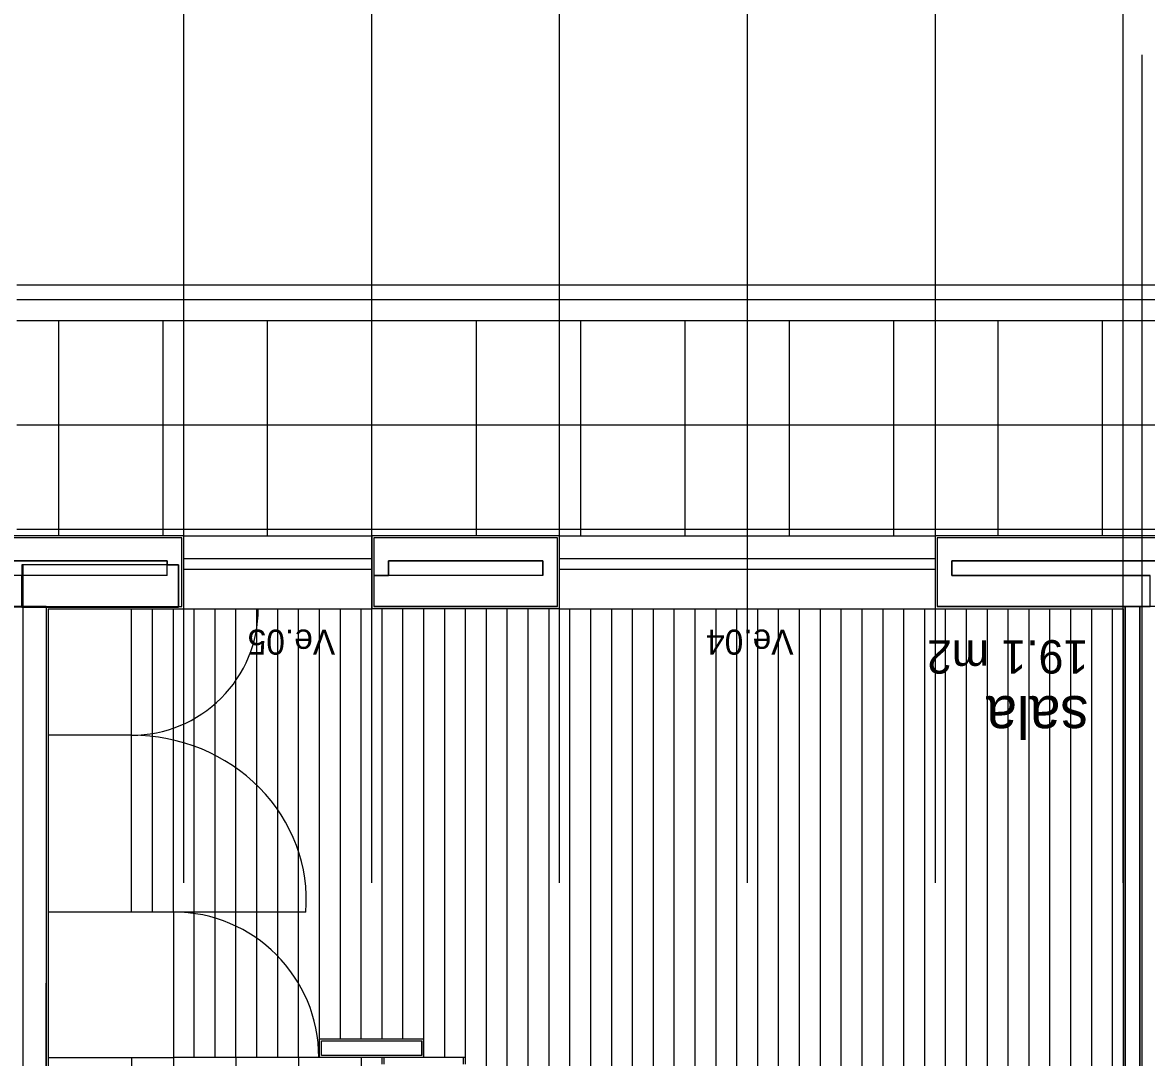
# Model space of a CAD drawing. Extents: x 1248 to 1356, y -443 to -224.
# Drawn here: x 1334.72 to 1340.11, y -234.42 to -229.47 of the extents above; entities that cross this region are included whole.
import ezdxf

# ---------------------------------------------------------------- set-up
doc = ezdxf.new("R2010")
doc.units = 0
for name, color, linetype in [('corte', 7, 'Continuous'), ('estereoctomias', 7, 'Continuous'), ('Level 1', 7, 'Continuous'), ('Level 10', 7, 'Continuous'), ('Level 13', 7, 'Continuous'), ('Level 2', 7, 'Continuous'), ('Level 3', 7, 'Continuous'), ('Level 4', 7, 'Continuous'), ('Level 40', 7, 'Continuous'), ('Level 60', 7, 'Continuous'), ('revestimentos', 7, 'Continuous'), ('vermelhos-cont', 7, 'Continuous'), ('vermelhos-tracej', 7, 'Continuous')]:
    doc.layers.add(name, color=color, linetype=linetype)

msp = doc.modelspace()

# ---------------------------------------------------------------- linework, layer by layer
at = {"layer": 'corte'}
for p, q in [((1335.484, -231.934), (1333.704, -231.934)), ((1337.284, -231.934), (1336.404, -231.934)), ((1340.884, -231.934), (1339.1033, -231.934)), ((1335.4133, -232.044), (1333.774, -232.044)), ((1337.214, -232.044), (1336.474, -232.044)), ((1340.814, -232.044), (1339.1733, -232.044)), ((1334.7233, -238.544), (1334.7233, -232.0639)), ((1335.4133, -232.114), (1334.7233, -232.114)), ((1337.214, -232.114), (1336.474, -232.114)), ((1339.1733, -232.114), (1340.1183, -232.114)), ((1334.8333, -232.264), (1333.704, -232.264)), ((1337.284, -232.264), (1336.404, -232.264)), ((1340.234, -232.264), (1339.1033, -232.264)), ((1340.0033, -238.424), (1340.0033, -232.264)), ((1340.0733, -236.7713), (1340.0733, -232.264))]:
    msp.add_line(p, q, dxfattribs=at)
msp.add_lwpolyline([(1335.4675, -232.0639), (1334.7175, -232.0639), (1334.7175, -232.2657), (1335.4675, -232.2657)], close=True, dxfattribs=at)
at = {"layer": 'estereoctomias'}
for points in [[(1334.7175, -232.2657), (1334.7175, -232.114), (1333.774, -232.114), (1333.774, -232.044), (1335.4133, -232.044), (1335.4133, -232.0639), (1335.4675, -232.0639), (1335.4675, -232.264), (1335.484, -232.264), (1335.484, -231.934), (1333.704, -231.934), (1333.704, -232.264)], [(1337.284, -232.264), (1337.284, -231.934), (1336.404, -231.934), (1336.404, -232.114), (1336.474, -232.114), (1336.474, -232.044), (1337.214, -232.044), (1337.214, -232.114), (1336.404, -232.114), (1336.404, -232.264)], [(1340.884, -232.264), (1340.884, -231.934), (1339.1033, -231.934), (1339.1033, -232.264), (1340.124, -232.264), (1340.124, -232.114), (1339.1733, -232.114), (1339.1733, -232.044), (1340.814, -232.044), (1340.814, -232.079), (1340.8683, -232.079), (1340.8683, -232.2657)], [(1334.8333, -235.8713), (1334.7233, -235.8713), (1334.7233, -232.264), (1334.8333, -232.264), (1334.8325, -235.8713)], [(1340.0733, -232.264), (1340.0733, -235.8713), (1340.0033, -235.8713), (1340.0033, -232.264)], [(1336.6333, -234.344), (1336.6333, -234.414), (1336.1533, -234.414), (1336.1533, -234.344)]]:
    msp.add_lwpolyline(points, close=True, dxfattribs=at)
at = {"layer": 'Level 1'}
for p, q in [((1335.484, -232.264), (1335.484, -231.934)), ((1336.404, -231.934), (1336.404, -232.264)), ((1337.284, -232.264), (1337.284, -231.934)), ((1339.1033, -231.934), (1339.1033, -232.264)), ((1335.4133, -232.114), (1335.4133, -232.044)), ((1336.474, -232.044), (1336.474, -232.114)), ((1337.214, -232.114), (1337.214, -232.044)), ((1339.1733, -232.044), (1339.1733, -232.114)), ((1334.7233, -232.114), (1334.7233, -232.114)), ((1334.8333, -232.264), (1335.484, -232.264)), ((1334.8333, -232.264), (1334.8333, -238.544)), ((1340.0033, -232.264), (1340.0033, -238.424)), ((1336.1533, -234.414), (1336.1533, -234.344)), ((1336.1533, -234.344), (1336.6333, -234.344)), ((1336.6333, -234.414), (1336.6333, -234.344)), ((1336.8433, -234.424), (1336.1433, -234.424)), ((1336.6333, -234.414), (1336.1533, -234.414)), ((1336.4433, -234.456), (1336.4433, -234.424)), ((1336.4533, -234.456), (1336.4533, -234.424)), ((1336.8333, -234.456), (1336.8333, -234.424)), ((1336.8433, -234.456), (1336.8433, -234.424))]:
    msp.add_line(p, q, dxfattribs=at)
at = {"layer": 'Level 10'}
for p, q in [((1340.0933, -230.894), (1334.6933, -230.894)), ((1334.8933, -230.894), (1334.8933, -231.924)), ((1335.3933, -230.894), (1335.3933, -231.924)), ((1335.8933, -230.894), (1335.8933, -231.924)), ((1336.3933, -230.894), (1336.3933, -231.924)), ((1336.8933, -230.894), (1336.8933, -231.924)), ((1337.3933, -230.894), (1337.3933, -231.924)), ((1337.8933, -230.894), (1337.8933, -231.924)), ((1338.3933, -230.894), (1338.3933, -231.924)), ((1338.8933, -230.894), (1338.8933, -231.924)), ((1339.3933, -230.894), (1339.3933, -231.924)), ((1339.8933, -230.894), (1339.8933, -231.924)), ((1345.4933, -230.894), (1340.0933, -230.894)), ((1340.0933, -231.394), (1334.6933, -231.394)), ((1345.4933, -231.394), (1340.0933, -231.394)), ((1340.0933, -231.894), (1334.6933, -231.894)), ((1345.4933, -231.894), (1340.0933, -231.894)), ((1335.3433, -233.727), (1335.3433, -232.274)), ((1335.4433, -233.727), (1335.4433, -232.274)), ((1335.5433, -234.424), (1335.5433, -232.274)), ((1335.6433, -234.424), (1335.6433, -232.274)), ((1335.7433, -234.424), (1335.7433, -232.274)), ((1335.8433, -234.424), (1335.8433, -232.274)), ((1335.9433, -234.424), (1335.9433, -232.274)), ((1336.0433, -234.424), (1336.0433, -232.274)), ((1336.1433, -234.334), (1336.1433, -232.274)), ((1336.2433, -234.334), (1336.2433, -232.274)), ((1336.3433, -234.334), (1336.3433, -232.274)), ((1336.4433, -234.334), (1336.4433, -232.274)), ((1336.5433, -234.334), (1336.5433, -232.274)), ((1336.6433, -234.334), (1336.6433, -232.274)), ((1336.7433, -234.424), (1336.7433, -232.274)), ((1336.8433, -234.424), (1336.8433, -232.274)), ((1336.9433, -238.409), (1336.9433, -232.274)), ((1337.0433, -238.409), (1337.0433, -232.274)), ((1337.1433, -238.409), (1337.1433, -232.274)), ((1337.2433, -238.409), (1337.2433, -232.274)), ((1337.3433, -238.409), (1337.3433, -232.274)), ((1337.4433, -238.409), (1337.4433, -232.274)), ((1337.5433, -236.624), (1337.5433, -232.274)), ((1337.6433, -236.624), (1337.6433, -232.274)), ((1337.7433, -236.624), (1337.7433, -232.274)), ((1337.8433, -236.624), (1337.8433, -232.274)), ((1337.9433, -236.624), (1337.9433, -232.274)), ((1338.0433, -236.624), (1338.0433, -232.274)), ((1338.1433, -236.624), (1338.1433, -232.274)), ((1338.2433, -236.624), (1338.2433, -232.274)), ((1338.3433, -236.624), (1338.3433, -232.274)), ((1338.4433, -236.624), (1338.4433, -232.274)), ((1338.5433, -236.624), (1338.5433, -232.274)), ((1338.6433, -236.624), (1338.6433, -232.274)), ((1338.7433, -236.624), (1338.7433, -232.274)), ((1338.8433, -236.624), (1338.8433, -232.274)), ((1338.9433, -236.624), (1338.9433, -232.274)), ((1339.0433, -236.624), (1339.0433, -232.274)), ((1339.1433, -236.624), (1339.1433, -232.274)), ((1339.2433, -236.624), (1339.2433, -232.274)), ((1339.3433, -236.624), (1339.3433, -232.274)), ((1339.4433, -236.624), (1339.4433, -232.274)), ((1339.5433, -236.624), (1339.5433, -232.274)), ((1339.6433, -236.624), (1339.6433, -232.274)), ((1339.7433, -236.624), (1339.7433, -232.274)), ((1339.8433, -236.624), (1339.8433, -232.274)), ((1339.9433, -236.624), (1339.9433, -232.274)), ((1336.1433, -234.424), (1335.4463, -234.424)), ((1335.7433, -234.424), (1335.7433, -236.824)), ((1336.0433, -234.424), (1336.0433, -236.824)), ((1336.3433, -234.424), (1336.3433, -236.824))]:
    msp.add_line(p, q, dxfattribs=at)
at = {"layer": 'Level 13'}
for p, q in [((1335.2433, -233.727), (1335.2433, -232.274)), ((1335.4433, -233.727), (1334.8433, -233.727)), ((1335.4433, -233.727), (1335.4433, -236.824))]:
    msp.add_line(p, q, dxfattribs=at)
at = {"layer": 'Level 2'}
for p, q in [((1340.0933, -230.724), (1334.6933, -230.724)), ((1345.4933, -230.724), (1340.0933, -230.724)), ((1340.0933, -230.794), (1334.6933, -230.794)), ((1345.4933, -230.794), (1340.0933, -230.794)), ((1335.494, -231.924), (1336.394, -231.924)), ((1337.294, -231.924), (1339.0933, -231.924)), ((1335.494, -232.034), (1336.394, -232.034)), ((1337.294, -232.034), (1339.0933, -232.034)), ((1335.494, -232.084), (1336.394, -232.084)), ((1337.294, -232.084), (1339.0933, -232.084)), ((1335.494, -232.274), (1336.394, -232.274)), ((1337.294, -232.274), (1339.0933, -232.274))]:
    msp.add_line(p, q, dxfattribs=at)
at = {"layer": 'Level 3'}
for q in [(1335.2433, -235.634), (1335.4433, -234.424)]:
    msp.add_line((1335.2433, -234.424), q, dxfattribs=at)
at = {"layer": 'Level 4'}
for p, q in [((1335.2433, -232.88), (1334.8433, -232.88)), ((1336.0783, -233.727), (1335.2433, -233.727)), ((1334.8433, -234.424), (1335.2433, -234.424))]:
    msp.add_line(p, q, dxfattribs=at)
msp.add_arc((1335.4433, -234.424), 0.697, 0, 90, dxfattribs=at)
for centre, major_axis, ratio, start_param, end_param in [((1335.2433, -232.274), (-0.6068, 0), 0.998761, 1.570796, 3.141593), ((1335.2433, -233.6703), (-0.8372, 0), 0.943954, 3.069792, 4.712389)]:
    msp.add_ellipse(centre, major_axis=major_axis, ratio=ratio, start_param=start_param, end_param=end_param, dxfattribs=at)
at = {"layer": 'revestimentos'}
for p, q in [((1335.494, -231.924), (1333.694, -231.924)), ((1335.494, -232.274), (1335.494, -231.924)), ((1336.394, -231.924), (1336.394, -232.274)), ((1337.294, -231.924), (1336.394, -231.924)), ((1337.294, -232.274), (1337.294, -231.924)), ((1340.894, -231.924), (1339.0933, -231.924)), ((1339.0933, -231.924), (1339.0933, -232.274)), ((1334.8433, -232.274), (1334.8433, -236.824)), ((1334.8433, -232.274), (1335.494, -232.274)), ((1337.294, -232.274), (1336.394, -232.274)), ((1339.0933, -232.274), (1339.9933, -232.274)), ((1339.9933, -232.274), (1339.9933, -238.424)), ((1336.1433, -234.334), (1336.6433, -234.334)), ((1336.1433, -234.424), (1336.1433, -234.334)), ((1336.6433, -234.424), (1336.6433, -234.334))]:
    msp.add_line(p, q, dxfattribs=at)
at = {"layer": 'vermelhos-cont'}
msp.add_line((1340.084, -229.6198), (1340.084, -250.7923), dxfattribs=at)
at = {"layer": 'vermelhos-tracej'}
for p, q in [((1335.494, -233.587), (1335.494, -228.3936)), ((1336.394, -233.587), (1336.394, -228.3936)), ((1337.294, -233.587), (1337.294, -228.3936)), ((1338.194, -233.587), (1338.194, -228.3936)), ((1339.094, -233.587), (1339.094, -228.3936)), ((1339.994, -233.587), (1339.994, -228.3936))]:
    msp.add_line(p, q, dxfattribs=at)

# ---------------------------------------------------------------- texts
at = {"layer": 'Level 40'}
for s, p in [('Ve.05', (1336.2186, -232.3738)), ('Ve.04', (1338.4148, -232.3738))]:
    msp.add_text(s, height=0.12, rotation=180, dxfattribs=at).set_placement(p)
at = {"layer": 'Level 60'}
for s, height, p in [('19.1 m2', 0.16, (1339.8269, -232.4246)), ('sala', 0.2, (1339.8269, -232.6924))]:
    msp.add_text(s, height=height, rotation=180, dxfattribs=at).set_placement(p)

doc.saveas('drawing.dxf')
